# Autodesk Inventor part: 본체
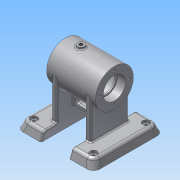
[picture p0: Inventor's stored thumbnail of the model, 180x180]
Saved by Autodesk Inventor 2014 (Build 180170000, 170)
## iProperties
Created: 2016-07
Part Number: 본체
Material: 알루미늄 6061
Document SubType Name: Modeling
Designer: Administrator
Density: 2.71 g/cm^3
Appearance: 알루미늄 - 평지
Mass: 512.163 g
Surface Area: 537.388 cm^2
Volume: 188.99 cm^3
Author: Administrator
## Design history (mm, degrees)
sketch "스케치1"
  geometry: C1 r 27 at (0, 0); 1 further point
  constraints: 1 centre point, 1 coincident
  dimensions: "d0" = 54 diameter of C1
extrude "돌출1" new body sketch "스케치1" stored distance "d1" = 70; taper "d2" = 0 deg
sketch "스케치2"
  geometry: C1 r 22 at (0, 0); 1 further point
  constraints: 1 centre point, 1 coincident
  dimensions: "d3" = 44 diameter of C1
extrude "돌출2" cut sketch "스케치2" stored distance "d4" = 42; taper "d5" = 0 deg
hole "구멍1" diameter "d8" = 32; stored, may be unused: countersink angle "d12" = 90 deg, drill point angle "d14" = 0 deg; dims "d6" = 10, "d7" = 10, "d9" = 6, "d10" = 4, "d11" = 2, "d13" = 12
hole "구멍2" diameter "d17" = 28; stored, may be unused: countersink angle "d21" = 90 deg, drill point angle "d23" = 0 deg; dims "d15" = 10, "d16" = 10, "d18" = 6, "d19" = 4, "d20" = 2, "d22" = 2
fillet "모깎기1" dims "d24" = 0.3
fillet "모깎기2" dims "d25" = 3
node "작업 평면1"
sketch "스케치3"
  geometry: L1 (-27, -35)-(27, -35) reference; C1 r 5 at (0, -13); 1 further point
  constraints: 1 centre point, 1 vertical alignment
  dimensions: "d28" = 22 distance from line of L1 C1.centre; "d29" = 10 diameter of C1
extrude "돌출3" join sketch "스케치3" stored distance "d30" = 42; taper "d31" = 0 deg
hole "구멍3" diameter "d34" = 5.188; stored, may be unused: countersink angle "d38" = 90 deg, drill point angle "d40" = 0 deg; dims "d32" = 10, "d33" = 10, "d35" = 6, "d36" = 4, "d37" = 2, "d39" = 2
sketch "스케치4" dims "d41" = 42
  geometry: C1 r 16 at (0, 0) reference; C2 r 27 at (0, 0) reference; 2 further points
  constraints: 2 vertical alignment, 1 coincident, 2 other
hole "구멍4" sketch "스케치4" at (0, 21) diameter "d42" = 3.242; stored, may be unused: countersink angle "d46" = 90 deg, drill point angle "d48" = 118 deg; dims "d43" = 8, "d44" = 4, "d45" = 2, "d47" = 10
sketch "스케치5"
  geometry: L1 (0, 0)-(0, -55.752); L2 (0, 0)-(15.898, -25.441)
  constraints: 4 end point, 1 vertical
  dimensions: "d52" = 32 deg angle of L1 L2; "d53" = 30 distance of L1.start L2.end
node "작업 평면2"
sketch "스케치6"
  geometry: C1 r 6 at (0, 0); 1 further point
  constraints: 1 centre point, 1 coincident
  dimensions: "d54" = 12 diameter of C1
extrude "돌출4" join sketch "스케치6" stored distance "d55" = 42; taper "d56" = 0 deg
hole "구멍5" diameter "d59" = 5.188; stored, may be unused: countersink angle "d63" = 90 deg, drill point angle "d65" = 0 deg; dims "d57" = 10, "d58" = 10, "d60" = 8, "d61" = 4, "d62" = 2, "d64" = 10
node "작업 평면8"
sketch "스케치17"
  geometry: L1 (27, 0)-(27, -70); L2 (27, -70)-(-27, -70); L3 (-27, -70)-(-27, 0); C1 r 27 at (0, 0) reference; A1 r 27 centre (0, 0) between (-27, 0) and (27, 0); 2 further points
  constraints: 8 end point, 2 point on circle, 1 centre point, 1 coincident, 1 concentric, 1 parallel, 1 vertical alignment
  dimensions: "d113" = 54 distance of L1.end L2.end; "d114" = 70 distance of L2.end L3.end; "d115" = 27 distance from line of point (0, -46.957) L3; "d116" = 46.95708 distance of point (0, 0) point (0, -46.957); "d117" = 70 distance of L1.start L1.end; "d118" = 23.04292 distance from line of L2 point (0, -46.957)
extrude "돌출11" join sketch "스케치17" distance "d119" = 8; taper "d120" = 0 deg
sketch "스케치19"
  geometry: L1 (-27, -70)-(27, -70) reference; L2 (-50, -58)-(50, -58); L3 (50, -58)-(50, -70); L4 (50, -70)-(-50, -70); L5 (-50, -70)-(-50, -58); 1 further point
  constraints: 8 end point, 2 midpoint, 2 parallel, 1 horizontal, 1 perpendicular
  dimensions: "d125" = 12 distance of L2.end L3.end; "d126" = 100 distance of L2.start L2.end
extrude "돌출13" join sketch "스케치19" distance "d127" = 35; taper "d128" = 0 deg
fillet "모깎기17" dims "d161" = 2
sketch "스케치25"
  geometry: L1 (100, 0)-(0, 0) reference; L2 (0, 0)-(0, 12) reference; L3 (0, 0)-(11.705, 32.159); L4 (0, 0)-(0, 32.159); L5 (0, 32.159)-(11.705, 32.159); 1 further point
  constraints: 6 end point, 1 collinear, 1 perpendicular
  dimensions: "d185" = 110 deg angle of L1 L3; "d186" = 11.70487 distance of L4.end L3.end
extrude "돌출17" cut sketch "스케치25" stored distance "d187" = 4; taper "d188" = 0 deg
sketch "스케치26"
  geometry: L1 (-70, 20)-(-70, 55) reference; L2 (-70, 55)-(-48.02, 47); L3 (-48.02, 47)-(-48.02, 55); L4 (-48.02, 55)-(-70, 55); 1 further point
  constraints: 6 end point, 1 parallel, 1 perpendicular
  dimensions: "d189" = 110 deg angle of L1 L2; "d190" = 8 distance of L2.end L3.end
extrude "돌출18" cut sketch "스케치26" stored distance "d191" = 4; taper "d192" = 0 deg
fillet "모깎기18" dims "d193" = 2
fillet "모깎기19" dims "d194" = 10
fillet "모깎기20" dims "d195" = 5
fillet "모깎기21" dims "d196" = 2
fillet "모깎기22" dims "d197" = 2
fillet "모깎기23" dims "d198" = 10
fillet "모깎기24" dims "d199" = 5
fillet "모깎기25" dims "d200" = 2
sketch "스케치27"
  geometry: L1 (-48, 22.07)-(-48, -22.07); L2 (-48, -22.07)-(-24.728, -22.07); L3 (-24.728, -22.07)-(-24.728, 22.07); L4 (-24.728, 22.07)-(-48, 22.07); L5 (-27, -35)-(-27, 35) reference; 2 further points
  constraints: 8 end point, 2 parallel, 1 horizontal alignment, 1 midpoint, 1 perpendicular, 1 vertical
  dimensions: "d201" = 44.13922 distance of L1.start L1.end; "d203" = 24.72753 distance from line of point (0, 0) L3; "d231" = 21 distance between parallel lines of L1 L5
extrude "돌출19" join sketch "스케치27" stored distance "d204" = 8; taper "d205" = 0 deg
sketch "스케치28"
  geometry: L1 (22, -70)-(45.603, -70) reference; L2 (-11.5, -34.5)-(11.5, -34.5); L3 (-11.5, -41.5)-(11.5, -41.5); A1 r 3.5 centre (-11.5, -38) between (-11.5, -41.5) and (-11.5, -34.5); A2 r 3.5 centre (11.5, -38) between (11.5, -41.5) and (11.5, -34.5); 1 further point
  constraints: 4 end point, 4 point on circle, 2 centre point, 2 parallel, 2 tangent, 1 horizontal alignment
  dimensions: "d207" = 32 distance from line of L1 A1.centre; "d208" = 23 distance of A1.centre A2.centre; "d209" = 11.5 horizontal distance of point (0, 0) A1.centre; "d210" = 7 diameter of A1; "d211" = 7 diameter of A2
extrude "돌출20" cut sketch "스케치28" stored distance "d212" = 8; taper "d213" = 0 deg
fillet "모깎기26" dims "d214" = 2
sketch "스케치29"
  geometry: C1 r 5 at (-12.5, -12.5); 1 further point
  constraints: 1 centre point
  dimensions: "d215" = 42.5 vertical distance of point (25, 30) C1.centre; "d216" = 37.5 horizontal distance of point (25, 30) C1.centre; "d217" = 10 diameter of C1
extrude "돌출21" cut sketch "스케치29" distance "d218" = 4; taper "d219" = 0 deg
hole "구멍7" diameter "d222" = 6; stored, may be unused: countersink angle "d226" = 90 deg, drill point angle "d228" = 0 deg; dims "d223" = 6, "d224" = 4, "d225" = 2, "d227" = 10, "d232" = 10, "d233" = 10
node "작업 평면10"
sketch "스케치30"
  geometry: 2 further points
  constraints: 1 coincident, 1 other
feature "엠보싱2" sketch "스케치30" dims "d234" = 0.5, "d235" = 0
node "솔리드1"
mirror "대칭1"
pattern_circular "원형 패턴1" dims angle "d50" = 360 deg
mirror "대칭2"
mirror "대칭5"
mirror "대칭8"
mirror "대칭9"
mirror "대칭10"
mirror "대칭11"
mirror "대칭12"
mirror "대칭13"
